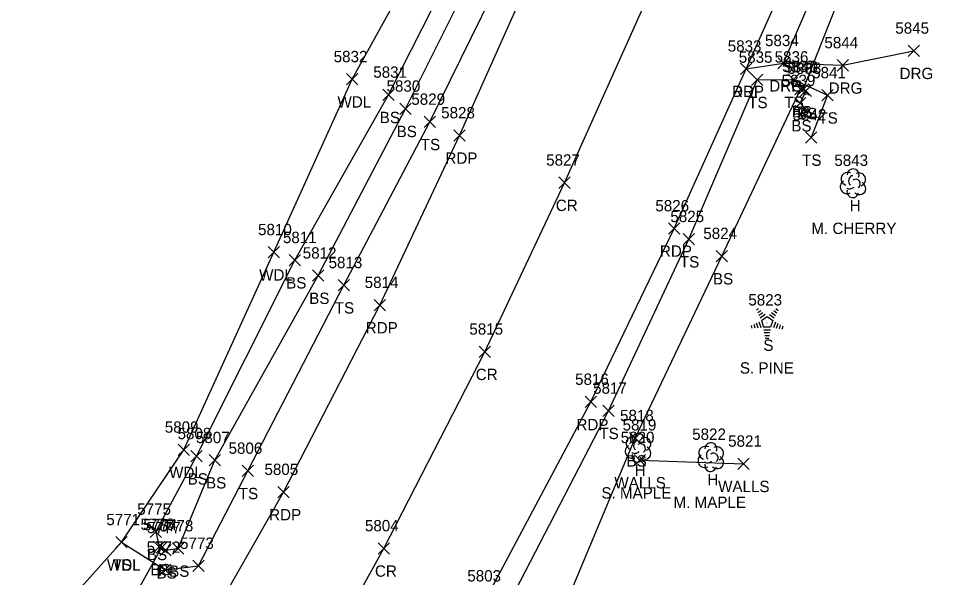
# Model space of a CAD drawing. Extents: x 1611797 to 1633212, y 298978 to 305475.
# Drawn here: x 1622570.5 to 1622734.6, y 301431.8 to 301530.3 of the extents above; entities that cross this region are included whole.
import ezdxf

# ---------------------------------------------------------------- set-up
doc = ezdxf.new("R2010")
doc.units = 0
for name, color, linetype in [('D_A', 7, 'Continuous'), ('D_I', 7, 'Continuous'), ('D_TIC', 7, 'Continuous'), ('DCP', 7, 'Continuous'), ('L_A', 7, 'Continuous'), ('L_C', 7, 'Continuous'), ('L_I', 7, 'Continuous'), ('L_TIC', 7, 'Continuous'), ('LAWA', 7, 'Continuous'), ('LELB', 7, 'Continuous'), ('LTC', 7, 'Continuous'), ('LTD', 7, 'Continuous'), ('LWS', 7, 'Continuous'), ('P_A', 7, 'Continuous'), ('P_I', 7, 'Continuous'), ('P_TIC', 7, 'Continuous'), ('PET', 7, 'Continuous'), ('PRC', 7, 'Continuous'), ('R_A', 7, 'Continuous'), ('R_I', 7, 'Continuous'), ('R_TIC', 7, 'Continuous'), ('RDG', 7, 'Continuous'), ('RDP', 7, 'Continuous')]:
    doc.layers.add(name, color=color, linetype=linetype)

msp = doc.modelspace()

# ---------------------------------------------------------------- linework, layer by layer
at = {"layer": 'D_TIC'}
for points in [[(1622707.82, 301516.78), (1622709.82, 301518.78)], [(1622709.82, 301516.78), (1622707.82, 301518.78)], [(1622594.74, 301436.07), (1622596.74, 301438.07)], [(1622596.74, 301436.07), (1622594.74, 301438.07)]]:
    msp.add_lwpolyline(points, dxfattribs=at)
at = {"layer": 'DCP'}
for points in [[(1622708.82, 301517.78), (1622718.35, 301541.87)], [(1622579.88, 301408.46), (1622595.74, 301437.07)]]:
    msp.add_lwpolyline(points, dxfattribs=at)
at = {"layer": 'L_TIC'}
for points in [[(1622628.31, 301518.57), (1622630.31, 301520.57)], [(1622630.31, 301518.57), (1622628.31, 301520.57)], [(1622706.11, 301518.51), (1622708.11, 301520.51)], [(1622708.11, 301518.51), (1622706.11, 301520.51)], [(1622699.72, 301518.47), (1622701.72, 301520.47)], [(1622701.72, 301518.47), (1622699.72, 301520.47)], [(1622634.73, 301515.83), (1622636.73, 301517.83)], [(1622636.73, 301515.83), (1622634.73, 301517.83)], [(1622707.37, 301516.84), (1622709.37, 301518.84)], [(1622709.37, 301516.84), (1622707.37, 301518.84)], [(1622708.31, 301516.52), (1622710.31, 301518.52)], [(1622710.31, 301516.52), (1622708.31, 301518.52)], [(1622712.09, 301515.74), (1622714.09, 301517.74)], [(1622714.09, 301515.74), (1622712.09, 301517.74)], [(1622707.29, 301514.37), (1622709.29, 301516.37)], [(1622709.29, 301514.37), (1622707.29, 301516.37)], [(1622637.71, 301513.37), (1622639.71, 301515.37)], [(1622639.71, 301513.37), (1622637.71, 301515.37)], [(1622642, 301511.06), (1622644, 301513.06)], [(1622644, 301511.06), (1622642, 301513.06)], [(1622709.22, 301508.3), (1622711.22, 301510.3)], [(1622711.22, 301508.3), (1622709.22, 301510.3)], [(1622687.67, 301490.39), (1622689.67, 301492.39)], [(1622689.67, 301490.39), (1622687.67, 301492.39)], [(1622614.5, 301488.08), (1622616.5, 301490.08)], [(1622616.5, 301488.08), (1622614.5, 301490.08)], [(1622693.47, 301487.4), (1622695.47, 301489.4)], [(1622695.47, 301487.4), (1622693.47, 301489.4)], [(1622618.23, 301486.68), (1622620.23, 301488.68)], [(1622620.23, 301486.68), (1622618.23, 301488.68)], [(1622622.3, 301483.96), (1622624.3, 301485.96)], [(1622624.3, 301483.96), (1622622.3, 301485.96)], [(1622626.84, 301482.27), (1622628.84, 301484.27)], [(1622628.84, 301482.27), (1622626.84, 301484.27)], [(1622673.48, 301460.14), (1622675.48, 301462.14)], [(1622675.48, 301460.14), (1622673.48, 301462.14)], [(1622678.22, 301455.3), (1622680.22, 301457.3)], [(1622680.22, 301455.3), (1622678.22, 301457.3)], [(1622598.63, 301453.27), (1622600.63, 301455.27)], [(1622600.63, 301453.27), (1622598.63, 301455.27)], [(1622600.87, 301452.13), (1622602.87, 301454.13)], [(1622602.87, 301452.13), (1622600.87, 301454.13)], [(1622604.11, 301451.44), (1622606.11, 301453.44)], [(1622606.11, 301451.44), (1622604.11, 301453.44)], [(1622679, 301451.45), (1622681, 301453.45)], [(1622681, 301451.45), (1622679, 301453.45)], [(1622697.28, 301450.8), (1622699.28, 301452.8)], [(1622699.28, 301450.8), (1622697.28, 301452.8)], [(1622609.92, 301449.55), (1622611.92, 301451.55)], [(1622611.92, 301449.55), (1622609.92, 301451.55)], [(1622593.68, 301438.81), (1622595.68, 301440.81)], [(1622595.68, 301438.81), (1622593.68, 301440.81)], [(1622593.68, 301438.81), (1622595.68, 301440.81)], [(1622595.68, 301438.81), (1622593.68, 301440.81)], [(1622587.66, 301436.97), (1622589.66, 301438.97)], [(1622589.66, 301436.97), (1622587.66, 301438.97)], [(1622587.66, 301436.97), (1622589.66, 301438.97)], [(1622589.66, 301436.97), (1622587.66, 301438.97)], [(1622594.31, 301436.14), (1622596.31, 301438.14)], [(1622596.31, 301436.14), (1622594.31, 301438.14)], [(1622595.39, 301435.56), (1622597.39, 301437.56)], [(1622597.39, 301435.56), (1622595.39, 301437.56)], [(1622597.61, 301435.87), (1622599.61, 301437.87)], [(1622599.61, 301435.87), (1622597.61, 301437.87)], [(1622595.34, 301432.1), (1622597.34, 301434.1)], [(1622597.34, 301432.1), (1622595.34, 301434.1)], [(1622601.23, 301432.79), (1622603.23, 301434.79)], [(1622603.23, 301432.79), (1622601.23, 301434.79)]]:
    msp.add_lwpolyline(points, dxfattribs=at)
at = {"layer": 'LAWA'}
msp.add_lwpolyline([(1622387.76, 301179.05), (1622397.07, 301179.12), (1622427.65, 301209.9), (1622449.62, 301231.58), (1622470.34, 301267.63), (1622492.33, 301297.51), (1622515.41, 301331.49), (1622538.47, 301358.93), (1622560.23, 301389.57), (1622576.72, 301416.07), (1622576.44, 301420.03), (1622578.56, 301426.68), (1622588.66, 301437.97), (1622599.63, 301454.27), (1622615.5, 301489.08), (1622629.31, 301519.57), (1622648.55, 301554.37)], dxfattribs=at)
at = {"layer": 'LELB'}
for points in [[(1622594.68, 301439.81), (1622595.31, 301437.14), (1622596.39, 301436.56), (1622598.61, 301436.87), (1622605.11, 301452.44), (1622623.3, 301484.96), (1622638.71, 301514.37), (1622656.97, 301550.94), (1622672.9, 301585.85), (1622690.2, 301620.98), (1622704.33, 301654.63), (1622718.47, 301691.01), (1622735.69, 301728.38), (1622751, 301766.72), (1622767.76, 301805.21), (1622781.52, 301838.57), (1622799.78, 301877.75), (1622815.96, 301917.88), (1622831.89, 301949.85), (1622847.11, 301991.62), (1622864.58, 302030.86), (1622881.19, 302073.91), (1622897.69, 302112.61), (1622900.36, 302148.59)], [(1622594.68, 301439.81), (1622601.87, 301453.13), (1622619.23, 301487.68), (1622635.73, 301516.83), (1622653.65, 301552.16), (1622669.95, 301587.77), (1622685.32, 301622.84), (1622699.32, 301657.33), (1622714.74, 301693.53), (1622730.88, 301731.3), (1622746.12, 301769.47), (1622759.32, 301807.94), (1622775.78, 301841.76), (1622793.88, 301879.63), (1622811.29, 301920.97), (1622825.77, 301951.79), (1622844.08, 301994.2), (1622859.8, 302033.13), (1622878.46, 302076.5), (1622894.74, 302113.74), (1622900.36, 302148.59)], [(1622588.66, 301437.97), (1622596.34, 301433.1), (1622602.23, 301433.79), (1622610.92, 301450.55), (1622627.84, 301483.27), (1622643, 301512.06), (1622661.31, 301549.35)], [(1622659.62, 301383.37), (1622644.87, 301402.07), (1622656.41, 301426.2), (1622674.48, 301461.14), (1622688.67, 301491.39), (1622700.72, 301519.47), (1622707.11, 301519.51), (1622713.09, 301516.74), (1622710.22, 301509.3)], [(1622662.94, 301391.46), (1622656, 301399.83), (1622664.56, 301421.33), (1622679.22, 301456.3), (1622694.47, 301488.4), (1622708.37, 301517.84), (1622709.31, 301517.52), (1622708.29, 301515.37)]]:
    msp.add_lwpolyline(points, dxfattribs=at)
at = {"layer": 'LTC'}
for p, q in [((1622700.61, 301478.9), (1622700.96, 301479.15)), ((1622700.82, 301478.43), (1622701.34, 301478.81)), ((1622701.03, 301477.96), (1622701.73, 301478.48)), ((1622701.23, 301477.5), (1622702.11, 301478.14)), ((1622702.89, 301478.09), (1622703.7, 301477.5)), ((1622703.26, 301478.44), (1622703.94, 301477.95)), ((1622703.63, 301478.79), (1622704.18, 301478.39)), ((1622704, 301479.14), (1622704.42, 301478.83)), ((1622700.09, 301476.39), (1622700.31, 301475.74)), ((1622700.55, 301476.61), (1622700.82, 301475.77)), ((1622701, 301476.82), (1622701.34, 301475.8)), ((1622701.46, 301477.04), (1622702.47, 301477.78)), ((1622701.46, 301477.04), (1622701.85, 301475.85)), ((1622702.47, 301477.78), (1622703.47, 301477.05)), ((1622703.47, 301477.05), (1622703.08, 301475.85)), ((1622703.91, 301476.78), (1622703.57, 301475.74)), ((1622704.35, 301476.53), (1622704.06, 301475.65)), ((1622704.79, 301476.28), (1622704.56, 301475.55)), ((1622699.64, 301476.17), (1622699.79, 301475.71)), ((1622703.08, 301475.85), (1622701.85, 301475.85)), ((1622703.04, 301475.35), (1622701.89, 301475.35)), ((1622702.95, 301474.85), (1622701.97, 301474.85)), ((1622705.24, 301476.03), (1622705.05, 301475.46)), ((1622702.87, 301474.35), (1622702.04, 301474.35)), ((1622702.79, 301473.85), (1622702.11, 301473.85))]:
    msp.add_line(p, q, dxfattribs=at)
at = {"layer": 'LTD'}
for p, q in [((1622717.57, 301501.29), (1622717.57, 301501.29)), ((1622717.57, 301501.29), (1622717.57, 301501.29)), ((1622679.68, 301454.66), (1622679.68, 301454.66)), ((1622679.68, 301454.66), (1622679.68, 301454.66)), ((1622692.51, 301453.01), (1622692.51, 301453.01)), ((1622692.51, 301453.01), (1622692.51, 301453.01))]:
    msp.add_line(p, q, dxfattribs=at)
for centre in [(1622717.62, 301502.72), (1622679.72, 301456.1), (1622692.56, 301454.44)]:
    msp.add_arc(centre, 1.05, 335.5272, 180.9563, dxfattribs=at)
for centre, major_axis, ratio, start_param, end_param in [((1622716.78, 301501.96), (1.21, -0.51), 0.895232, 1.570796, 4.712389), ((1622717.36, 301501.75), (-0.208, -0.792), 0.645439, 3.141593, 6.283185), ((1622718.61, 301501.87), (-1.14, -0.48), 0.949671, 1.570796, 4.712389), ((1622716.49, 301500.58), (0.58, -1.04), 0.959034, 3.141593, 6.283185), ((1622718.07, 301501.12), (-0.5, 0.667), 0.989748, 3.141593, 6.283185), ((1622718.57, 301500.46), (-1.09, 0.79), 0.841452, 1.570796, 4.712389), ((1622717.57, 301499.79), (0.26, 1.06), 0.942809, 1.570796, 4.712389), ((1622717.11, 301500.54), (-0.625, -0.083), 0.423636, 0, 3.141593), ((1622678.89, 301455.33), (1.21, -0.51), 0.895232, 1.570796, 4.712389), ((1622680.72, 301455.25), (-1.14, -0.48), 0.949671, 1.570796, 4.712389), ((1622678.59, 301453.96), (0.58, -1.04), 0.959034, 3.141593, 6.283185), ((1622679.47, 301455.12), (-0.208, -0.792), 0.645439, 3.141593, 6.283185), ((1622680.18, 301454.5), (-0.5, 0.667), 0.989748, 3.141593, 6.283185), ((1622691.72, 301453.67), (1.21, -0.51), 0.895232, 1.570796, 4.712389), ((1622693.55, 301453.59), (-1.14, -0.48), 0.949671, 1.570796, 4.712389), ((1622679.68, 301453.16), (0.26, 1.06), 0.942809, 1.570796, 4.712389), ((1622679.22, 301453.91), (-0.625, -0.083), 0.423636, 0, 3.141593), ((1622680.68, 301453.83), (-1.09, 0.79), 0.841452, 1.570796, 4.712389), ((1622691.43, 301452.3), (0.58, -1.04), 0.959034, 3.141593, 6.283185), ((1622692.3, 301453.46), (-0.208, -0.792), 0.645439, 3.141593, 6.283185), ((1622693.01, 301452.84), (-0.5, 0.667), 0.989748, 3.141593, 6.283185), ((1622692.51, 301451.51), (0.26, 1.06), 0.942809, 1.570796, 4.712389), ((1622692.05, 301452.25), (-0.625, -0.083), 0.423636, 0, 3.141593), ((1622693.51, 301452.17), (-1.09, 0.79), 0.841452, 1.570796, 4.712389)]:
    msp.add_ellipse(centre, major_axis=major_axis, ratio=ratio, start_param=start_param, end_param=end_param, dxfattribs=at)
at = {"layer": 'LWS'}
msp.add_lwpolyline([(1622680, 301452.45), (1622698.28, 301451.8)], dxfattribs=at)
at = {"layer": 'P_TIC'}
for points in [[(1622697.78, 301520.43), (1622699.78, 301522.43)], [(1622699.78, 301520.43), (1622697.78, 301522.43)], [(1622647.26, 301508.67), (1622649.26, 301510.67)], [(1622649.26, 301508.67), (1622647.26, 301510.67)], [(1622665.77, 301500.34), (1622667.77, 301502.34)], [(1622667.77, 301500.34), (1622665.77, 301502.34)], [(1622685.07, 301492.28), (1622687.07, 301494.28)], [(1622687.07, 301492.28), (1622685.07, 301494.28)], [(1622633.21, 301478.77), (1622635.21, 301480.77)], [(1622635.21, 301478.77), (1622633.21, 301480.77)], [(1622651.67, 301470.55), (1622653.67, 301472.55)], [(1622653.67, 301470.55), (1622651.67, 301472.55)], [(1622670.36, 301461.7), (1622672.36, 301463.7)], [(1622672.36, 301461.7), (1622670.36, 301463.7)], [(1622616.19, 301445.82), (1622618.19, 301447.82)], [(1622618.19, 301445.82), (1622616.19, 301447.82)], [(1622633.9, 301435.89), (1622635.9, 301437.89)], [(1622635.9, 301435.89), (1622633.9, 301437.89)]]:
    msp.add_lwpolyline(points, dxfattribs=at)
at = {"layer": 'PET'}
for points in [[(1622408.25, 301165.87), (1622439.39, 301198.04), (1622461.95, 301222.58), (1622487.93, 301253.76), (1622511.51, 301284.23), (1622534.35, 301314.53), (1622556.78, 301346.23), (1622577.91, 301378.88), (1622595.01, 301407.43), (1622603.73, 301423.2), (1622617.19, 301446.82), (1622634.21, 301479.77), (1622648.26, 301509.67), (1622665.21, 301547.65)], [(1622403.36, 301105.61), (1622435.21, 301136.14), (1622468.93, 301170.7), (1622500.38, 301205.45), (1622521.19, 301230.71), (1622543.38, 301258.33), (1622567.24, 301290.95), (1622590.49, 301324.58), (1622611.08, 301357.32), (1622628.6, 301384.44), (1622639.72, 301403.14), (1622652.95, 301428.05), (1622671.36, 301462.7), (1622686.07, 301493.28), (1622698.78, 301521.43), (1622708.15, 301542.48)]]:
    msp.add_lwpolyline(points, dxfattribs=at)
at = {"layer": 'PRC'}
msp.add_lwpolyline([(1622391.65, 301120.64), (1622424.38, 301151.76), (1622455.13, 301183.21), (1622477.75, 301209.09), (1622504, 301239.92), (1622528.25, 301271.13), (1622551.53, 301302.46), (1622573.96, 301335.04), (1622594.86, 301367.38), (1622615.3, 301401.53), (1622634.9, 301436.89), (1622652.67, 301471.55), (1622666.77, 301501.34), (1622684.44, 301540.78)], dxfattribs=at)
at = {"layer": 'R_TIC'}
for points in [[(1622727.32, 301523.59), (1622729.32, 301525.59)], [(1622729.32, 301523.59), (1622727.32, 301525.59)], [(1622697.78, 301520.43), (1622699.78, 301522.43)], [(1622699.78, 301520.43), (1622697.78, 301522.43)], [(1622704.35, 301521.4), (1622706.35, 301523.4)], [(1622706.35, 301521.4), (1622704.35, 301523.4)], [(1622704.35, 301521.4), (1622706.35, 301523.4)], [(1622706.35, 301521.4), (1622704.35, 301523.4)], [(1622714.82, 301521.02), (1622716.82, 301523.02)], [(1622716.82, 301521.02), (1622714.82, 301523.02)]]:
    msp.add_lwpolyline(points, dxfattribs=at)
at = {"layer": 'RDG'}
msp.add_lwpolyline([(1622705.35, 301522.4), (1622715.82, 301522.02), (1622728.32, 301524.59)], dxfattribs=at)
at = {"layer": 'RDP'}
msp.add_lwpolyline([(1622698.78, 301521.43), (1622705.35, 301522.4), (1622711.64, 301537.06), (1622708.15, 301542.48)], dxfattribs=at)

# ---------------------------------------------------------------- texts
at = {"layer": 'D_A'}
for p in [(1622708.2, 301512.78), (1622595.12, 301432.07)]:
    msp.add_text('P', height=2, dxfattribs=at).set_placement(p)
at = {"layer": 'D_I'}
for s, p in [('5840', (1622705.47, 301520.78)), ('5774', (1622592.48, 301440.07))]:
    msp.add_text(s, height=2, dxfattribs=at).set_placement(p)
at = {"layer": 'L_A'}
for s, p in [('WDL', (1622626.72, 301514.57)), ('TS', (1622699.13, 301514.47)), ('TS', (1622705.52, 301514.51)), ('BS', (1622706.81, 301512.84)), ('BS', (1622707.76, 301512.52)), ('BS', (1622634.17, 301511.83)), ('BS', (1622706.73, 301510.37)), ('TS', (1622711.5, 301511.74)), ('BS', (1622637.15, 301509.37)), ('TS', (1622641.41, 301507.06)), ('TS', (1622708.63, 301504.3)), ('H', (1622717, 301496.29)), ('TS', (1622687.08, 301486.39)), ('WDL', (1622612.91, 301484.08)), ('BS', (1622617.67, 301482.68)), ('BS', (1622692.91, 301483.4)), ('BS', (1622621.74, 301479.96)), ('TS', (1622626.25, 301478.27)), ('S', (1622701.8, 301471.69)), ('TS', (1622672.89, 301456.14)), ('BS', (1622677.66, 301451.3)), ('H', (1622679.11, 301449.66)), ('WDL', (1622597.04, 301449.27)), ('BS', (1622600.31, 301448.13)), ('H', (1622691.94, 301448.01)), ('BS', (1622603.55, 301447.44)), ('WALLS', (1622675.54, 301447.45)), ('WALLS', (1622693.82, 301446.8)), ('TS', (1622609.33, 301445.55)), ('BS', (1622593.12, 301434.81)), ('BS', (1622593.12, 301434.81)), ('WDL', (1622586.08, 301432.97)), ('TS', (1622587.07, 301432.97)), ('BS', (1622593.76, 301432.14)), ('BS', (1622594.83, 301431.56)), ('BS', (1622597.05, 301431.87))]:
    msp.add_text(s, height=2, dxfattribs=at).set_placement(p)
at = {"layer": 'L_C'}
for s, p in [('M. CHERRY', (1622710.26, 301492.29)), ('S. PINE', (1622697.66, 301467.69)), ('S. MAPLE', (1622673.25, 301445.66)), ('M. MAPLE', (1622685.96, 301444.01))]:
    msp.add_text(s, height=2, dxfattribs=at).set_placement(p)
at = {"layer": 'L_I'}
for s, p in [('5832', (1622626.05, 301522.57)), ('5835', (1622697.46, 301522.47)), ('5836', (1622703.79, 301522.51)), ('5837', (1622705.11, 301520.84)), ('5838', (1622706.06, 301520.52)), ('5831', (1622633.03, 301519.83)), ('5841', (1622710.4, 301519.74)), ('5830', (1622635.37, 301517.37)), ('5839', (1622705.02, 301518.37)), ('5829', (1622639.74, 301515.06)), ('5842', (1622706.96, 301512.3)), ('5843', (1622714.31, 301504.29)), ('5825', (1622685.41, 301494.39)), ('5810', (1622612.72, 301492.08)), ('5811', (1622617.1, 301490.68)), ('5824', (1622691.21, 301491.4)), ('5812', (1622620.6, 301487.96)), ('5813', (1622625.15, 301486.27)), ('5823', (1622699.15, 301479.69)), ('5817', (1622671.79, 301464.14)), ('5818', (1622676.53, 301459.3)), ('5809', (1622596.28, 301457.27)), ('5808', (1622598.53, 301456.13)), ('5819', (1622676.98, 301457.66)), ('5807', (1622601.77, 301455.44)), ('5820', (1622676.65, 301455.45)), ('5822', (1622689.25, 301456.01)), ('5821', (1622695.59, 301454.8)), ('5806', (1622607.52, 301453.55)), ('5775', (1622591.42, 301442.81)), ('5775', (1622591.42, 301442.81)), ('5771', (1622585.97, 301440.97)), ('5771', (1622585.97, 301440.97)), ('5776', (1622592, 301440.14)), ('5778', (1622595.35, 301439.87)), ('5777', (1622593.13, 301439.56)), ('5773', (1622598.97, 301436.79)), ('5772', (1622593.08, 301436.1))]:
    msp.add_text(s, height=2, dxfattribs=at).set_placement(p)
at = {"layer": 'LTC'}
msp.add_text('.', height=1.04, rotation=270, dxfattribs=at).set_placement((1622702.35, 301476.79))
at = {"layer": 'P_A'}
for s, p in [('RDP', (1622696.27, 301516.43)), ('RDP', (1622645.75, 301504.67)), ('CR', (1622665.21, 301496.34)), ('RDP', (1622683.56, 301488.28)), ('RDP', (1622631.7, 301474.77)), ('CR', (1622651.1, 301466.55)), ('RDP', (1622668.85, 301457.7)), ('RDP', (1622614.68, 301441.82)), ('CR', (1622633.33, 301431.89))]:
    msp.add_text(s, height=2, dxfattribs=at).set_placement(p)
at = {"layer": 'P_I'}
for s, p in [('5833', (1622695.52, 301524.43)), ('5828', (1622645, 301512.67)), ('5827', (1622663.51, 301504.34)), ('5826', (1622682.76, 301496.28)), ('5814', (1622631.52, 301482.77)), ('5815', (1622649.97, 301474.55)), ('5816', (1622668.61, 301465.7)), ('5805', (1622613.85, 301449.82)), ('5804', (1622631.56, 301439.89)), ('5803', (1622649.61, 301431.05))]:
    msp.add_text(s, height=2, dxfattribs=at).set_placement(p)
at = {"layer": 'R_A'}
for s, p in [('DRG', (1622725.81, 301519.59)), ('DRG', (1622702.84, 301517.4)), ('DRP', (1622702.84, 301517.4)), ('DRG', (1622713.31, 301517.02)), ('DRP', (1622696.27, 301516.43))]:
    msp.add_text(s, height=2, dxfattribs=at).set_placement(p)
at = {"layer": 'R_I'}
for s, p in [('5845', (1622725.06, 301527.59)), ('5834', (1622702.09, 301525.4)), ('5834', (1622702.09, 301525.4)), ('5844', (1622712.56, 301525.02)), ('5833', (1622695.52, 301524.43))]:
    msp.add_text(s, height=2, dxfattribs=at).set_placement(p)

doc.saveas('drawing.dxf')
